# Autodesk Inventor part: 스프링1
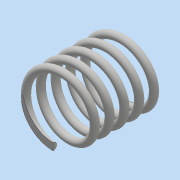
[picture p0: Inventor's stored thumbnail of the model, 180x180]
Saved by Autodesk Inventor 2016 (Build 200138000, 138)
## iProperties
Created: 2019-11
Part Number: 스프링1
Material: 일반
Document SubType Name: Modeling
Designer: user
Density: 1 g/cm^3
Appearance: 기본값
Mass: 0.821565 g
Surface Area: 16.7217 cm^2
Volume: 0.821565 cm^3
Author: user
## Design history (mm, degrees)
sketch "스케치1"
  geometry: L1 (0, 0)-(20.5, 0); L2 (20.5, 0)-(20.5, -8.5); L3 (20.5, -8.5)-(0, -8.5); L4 (0, -8.5)-(0, 0); C1 r 1 at (0, -8.5)
  constraints: 8 end point, 2 parallel, 1 centre point, 1 coincident, 1 horizontal, 1 perpendicular
  dimensions: "d0" = 20.5 distance of L1.start L1.end (derived); "d1" = 17 diameter of L3 L1; "d2" = 2 diameter of C1
feature "코일1" sketch "스케치1" pitch "d3" = 10; turns "d5" = 5; dims "d4" = 20.5 (= d0), "d6" = 0, angle "d7" = 90 deg, angle "d8" = 90 deg, "d9" = 0, "d10" = 0
sketch "스케치2"
  geometry: L1 (-15.996, 0)-(15.996, 0); L2 (15.996, 0)-(15.996, 20.5); L3 (15.996, 20.5)-(-15.996, 20.5); L4 (-15.996, 20.5)-(-15.996, 0); 2 further points
  constraints: 8 end point, 2 parallel, 1 coincident, 1 horizontal, 1 midpoint, 1 perpendicular
  dimensions: "d12" = 31.99189 distance between parallel lines of L2 L4; "d13" = 20.5 distance of L1.end L2.end (= d0)
extrude "돌출1" sketch "스케치2" stored distance "d14" = 38.25; taper "d15" = 0 deg
node "솔리드1"
